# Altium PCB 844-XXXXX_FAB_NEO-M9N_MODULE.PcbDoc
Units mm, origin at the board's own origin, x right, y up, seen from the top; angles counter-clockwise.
Board outline 67.18 x 31.75 mm, 4 copper layers (L01-Top Layer, L02-Inner Layer, L03-Inner Layer, L04-Bottom Layer), stack 1.555 mm thick; 33 components, 25 nets, 85 pads, 218 vias.
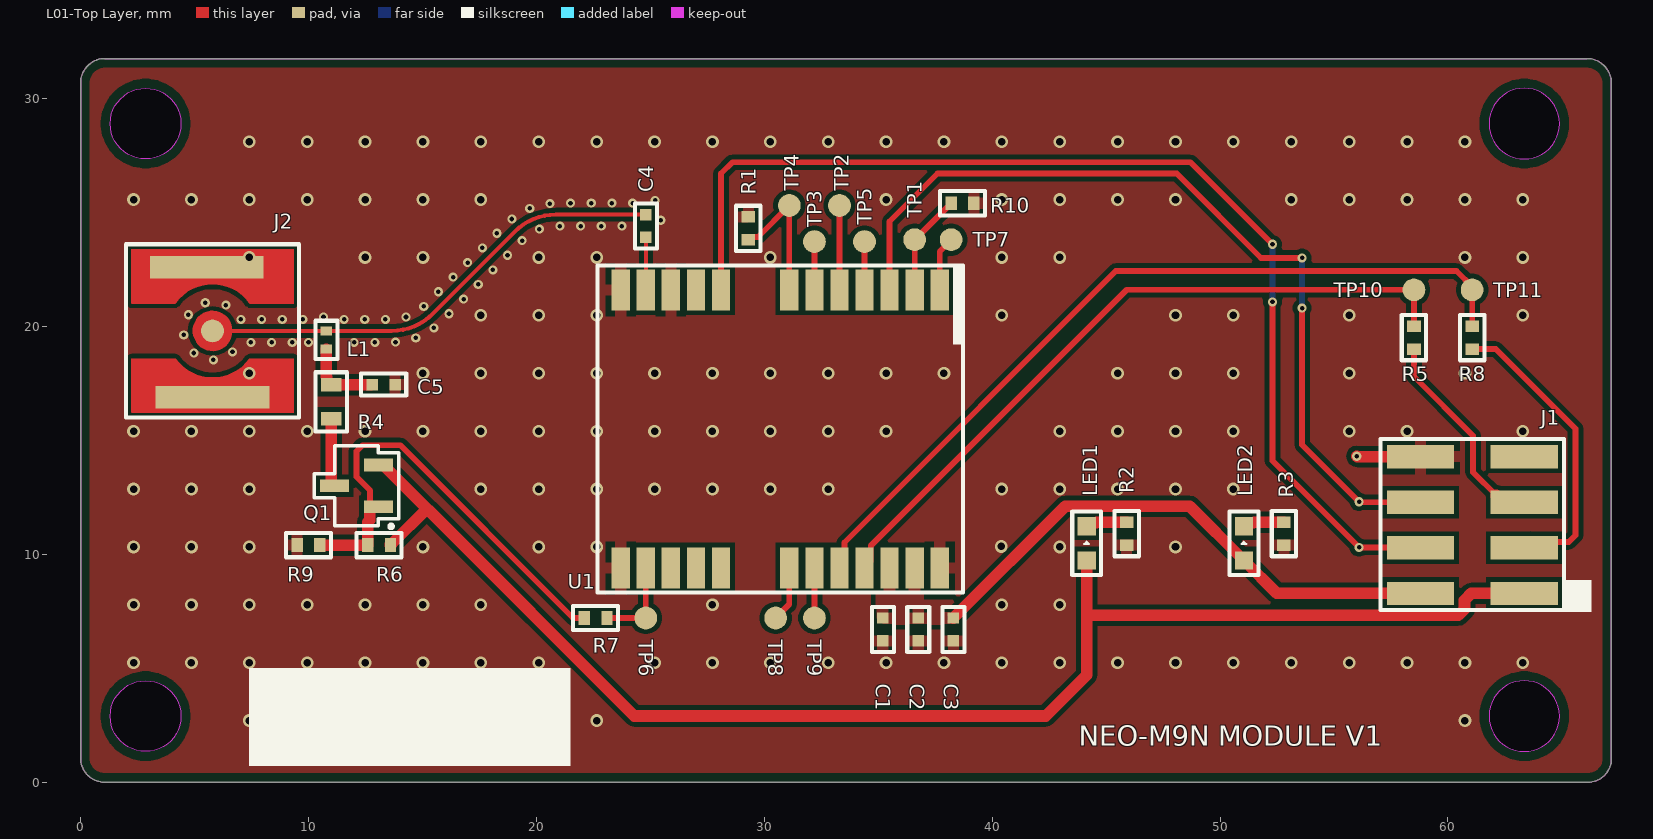
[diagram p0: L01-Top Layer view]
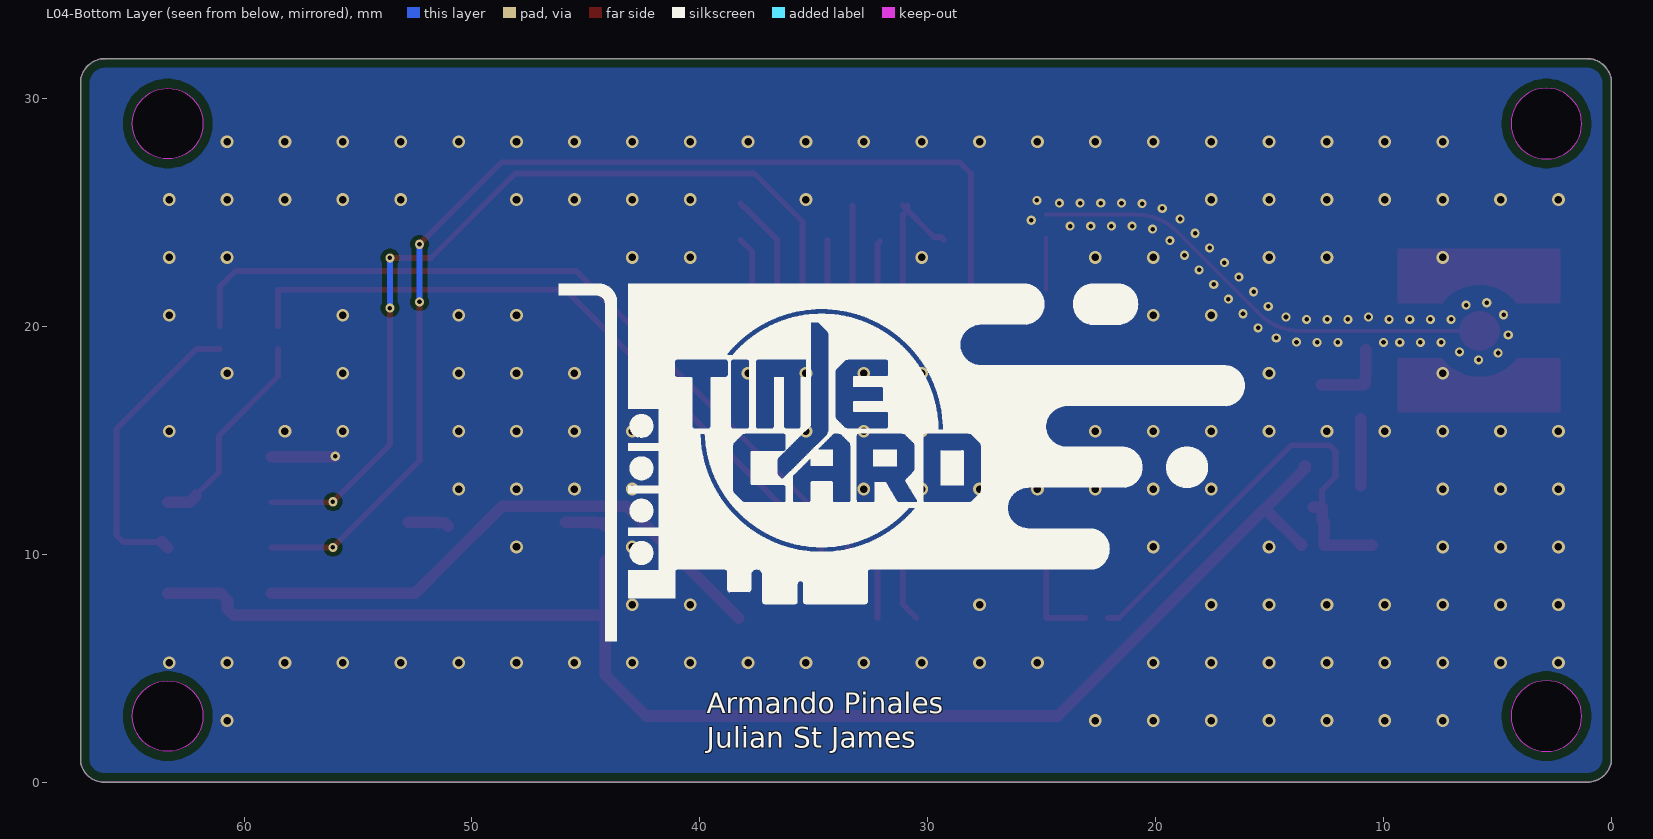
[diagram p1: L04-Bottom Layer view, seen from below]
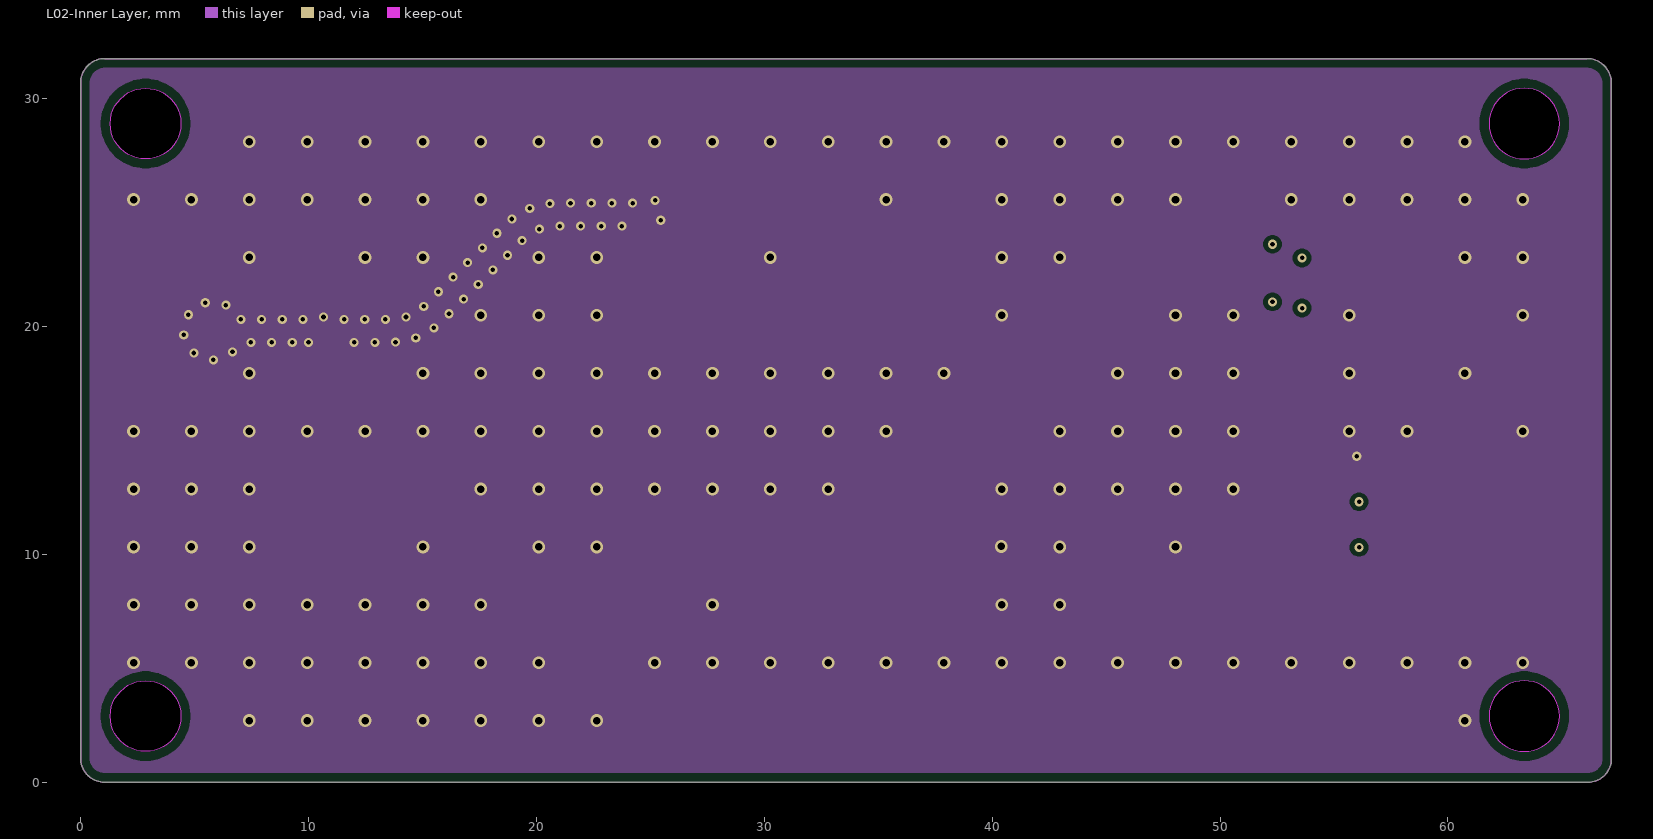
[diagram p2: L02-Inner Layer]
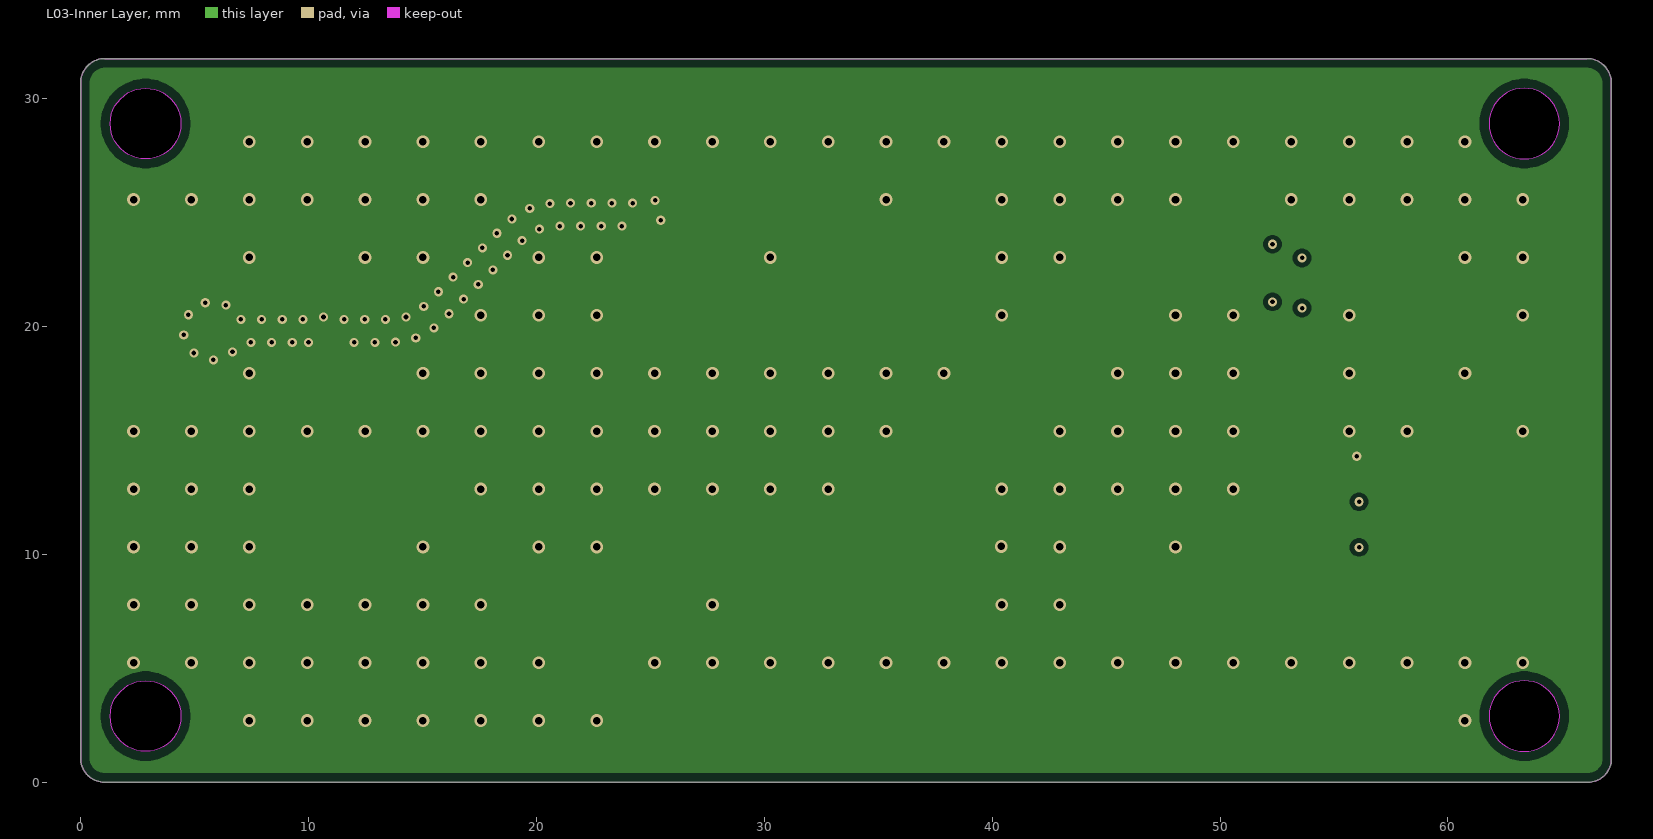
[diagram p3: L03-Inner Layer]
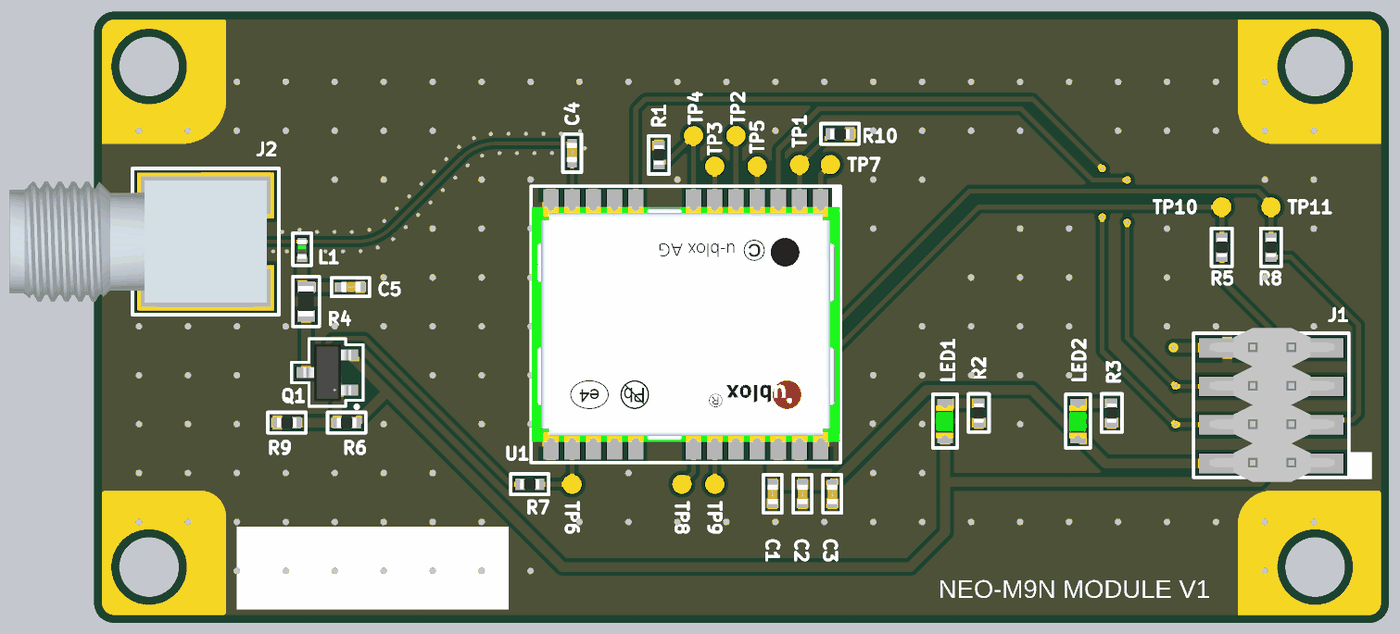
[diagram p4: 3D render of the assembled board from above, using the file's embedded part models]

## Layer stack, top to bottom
Top Solder: solder mask 0.0152, Solder Resist, Dk 3.9
L01-Top Layer: signal copper 0.0457
Dielectric 1: prepreg 0.1046, 2x106, Dk 3.7
L02-Inner Layer: signal copper 0.0305
Dielectric 2: core 1.1938, FR4, Dk 4.04
L03-Inner Layer: signal copper 0.0305
Dielectric 3: prepreg 0.1046, 2x106, Dk 3.7
L04-Bottom Layer: signal copper 0.0457
Bottom Solder: solder mask 0.0152, Solder Resist, Dk 3.9

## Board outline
1.045,0 cw(c1.045,1.045) 0,1.045 -0.002,30.676 cw(c1.069,30.676) 1.068,31.747 66.094,31.749 cw(c66.094,30.669) 67.174,30.67 67.171,1.015 cw(c66.152,1.015) 66.153,-0.004
cut-out: 61.801,2.896 ccw(c63.351,2.896) 63.351,1.346 ccw(c63.351,2.896) 64.901,2.896 ccw(c63.351,2.896) 63.351,4.446 ccw(c63.351,2.896)
cut-out: 1.301,2.896 cw(c2.851,2.896) 2.851,4.446 cw(c2.851,2.896) 4.401,2.896 cw(c2.851,2.896) 2.851,1.346 cw(c2.851,2.896)
cut-out: 61.801,28.896 ccw(c63.351,28.896) 63.351,27.346 ccw(c63.351,28.896) 64.901,28.896 ccw(c63.351,28.896) 63.351,30.446 ccw(c63.351,28.896)
cut-out: 2.851,27.346 cw(c2.851,28.896) 1.301,28.896 cw(c2.851,28.896) 2.851,30.446 cw(c2.851,28.896) 4.401,28.896 cw(c2.851,28.896)

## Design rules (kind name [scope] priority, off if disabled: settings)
AcuteAngle [All] p1: minimum=6.00000000000000E+0001 checktracksonly=FALSE
BoardOutlineClearance [All] p1: gap=0.4 ignorepadtopadclearanceinfootprint=FALSE
Clearance Clearance_L1andL4_Copper [(InPolygon AND (OnLayer('Top Layer') OR OnLayer('Bottom Layer'))) vs (InDifferentialPairClass('All Differential Pairs'))] p1: gap=0.2 ignorepadtopadclearanceinfootprint=FALSE except(0.3: Arc-Hole Track-Hole SMDPad-Hole THPad-Hole Via-Hole Fill-Hole Poly-Hole Region-Hole Text-Hole; 0.5: Arc-Fill Arc-Poly Arc-Region Track-Fill Track-Poly Track-Region SMDPad-Fill SMDPad-Poly SMDPad-Region THPad-Fill THPad-Poly THPad-Region Via-Fill Via-Poly Via-Region Fill-Fill Fill-Poly Fill-Region Poly-Poly Poly-Region Region-Region)
Clearance [All] p2: gap=0.2 ignorepadtopadclearanceinfootprint=FALSE
ComponentClearance [All] p1: gap=0.4 collisioncheckmode=3 verticalgap=0.5 showdistances=FALSE
DiffPairsRouting 90_Ohm_L1andL4 [InDifferentialPairClass('90_Ohm')] p1: maxlimit=0.254 minlimit=0.14 mostfreqgap=0.254 toplayer_maxgap=0.14 toplayer_prefgap=0.14 toplayer_minwidth=0.114 toplayer_maxwidth=0.114 toplayer_prefwidth=0.114 midlayer1_mingap=0.254 midlayer1_minwidth=0.381 midlayer1_maxwidth=0.381 midlayer1_prefwidth=0.381 midlayer2_mingap=0.254 midlayer2_minwidth=0.381 midlayer2_maxwidth=0.381 midlayer2_prefwidth=0.381 bottomlayer_maxgap=0.14 bottomlayer_prefgap=0.14 bottomlayer_minwidth=0.114 bottomlayer_maxwidth=0.114 bottomlayer_prefwidth=0.114 maxuncoupledlength=5.08
DiffPairsRouting 100_Ohm_L1andL4 [InDifferentialPairClass('100_Ohm')] p2: maxlimit=0.254 minlimit=0.241 mostfreqgap=0.254 toplayer_maxgap=0.241 toplayer_prefgap=0.241 toplayer_minwidth=0.114 toplayer_maxwidth=0.114 toplayer_prefwidth=0.114 midlayer1_mingap=0.254 midlayer1_minwidth=0.381 midlayer1_maxwidth=0.381 midlayer1_prefwidth=0.381 midlayer2_mingap=0.254 midlayer2_minwidth=0.381 midlayer2_maxwidth=0.381 midlayer2_prefwidth=0.381 bottomlayer_maxgap=0.241 bottomlayer_prefgap=0.241 bottomlayer_minwidth=0.114 bottomlayer_maxwidth=0.114 bottomlayer_prefwidth=0.114 maxuncoupledlength=5.08
DiffPairsRouting 100_Ohm_Default [All] p3: maxlimit=0.254 minlimit=0.241 mostfreqgap=0.254 toplayer_maxgap=0.241 toplayer_prefgap=0.241 toplayer_minwidth=0.114 toplayer_maxwidth=0.114 toplayer_prefwidth=0.114 midlayer1_mingap=0.254 midlayer1_minwidth=0.381 midlayer1_maxwidth=0.381 midlayer1_prefwidth=0.381 midlayer2_mingap=0.254 midlayer2_minwidth=0.381 midlayer2_maxwidth=0.381 midlayer2_prefwidth=0.381 bottomlayer_maxgap=0.241 bottomlayer_prefgap=0.241 bottomlayer_minwidth=0.114 bottomlayer_maxwidth=0.114 bottomlayer_prefwidth=0.114 maxuncoupledlength=5.08
HoleSize [All] p1: absolutevalues=TRUE maxlimit=3 minlimit=0.15 maxpercent=80.000 minpercent=20.000
HoleToHoleClearance [All] p1: gap=0.3 allowstackedmicrovias=TRUE
MatchedLengths [InDifferentialPairClass('All Differential Pairs')] p1: tolerance=0.025 checknetsindiffpair=TRUE checkdiffpairvsdiffpair=FALSE checkxsignals=FALSE checkothers=FALSE
MinimumSolderMaskSliver [All] p1: minsoldermaskwidth=0.1 // 0.076mm for Green Soldermask, 0.1 for other color soldermask
PlaneClearance [All] p1: clearance=0.254
PolygonConnect [All] p1: thpad.connectstyle=Relief thpad.reliefconductorwidth=0.508 thpad.reliefentries=4 thpad.polygonreliefangle="90 Angle" thpad.airgapwidth=0.254 smdpad.connectstyle=Relief smdpad.reliefconductorwidth=0.508 smdpad.reliefentries=4 smdpad.polygonreliefangle="90 Angle" smdpad.airgapwidth=0.254 via.connectstyle=Direct via.reliefconductorwidth=0.254 via.reliefentries=4 via.polygonreliefangle="90 Angle" via.airgapwidth=0.254
RoutingCorners [All] p1: cornerstyle=45-Degree minsetback=2.5 maxsetback=2.5
RoutingVias [All] p1: holewidth=0.2 width=0.4 viastyle="Through Hole" minholewidth=0.15 minwidth=0.35 maxholewidth=0.3 maxwidth=0.6
SilkToSilkClearance [All] p1: silktosilkclearance=0.1
SilkToSolderMaskClearance [IsPad] p1: minsilkscreentomaskgap=1 clearancetoexposedcopper=TRUE
SolderMaskExpansion [All] p1: expansion=0.05 istentingtop=FALSE
UnRoutedNet [All] p1: checkbadconnections=TRUE
Width Width_PWR [InNetClass('PWR')] p1: maxlimit=0.5 minlimit=0.2 preferedwidth=0.3 minimp=50.000000 maximp=50.000000 favimp=50.000000
Width Width_GND [InNetClass('GND')] p2: maxlimit=0.5 minlimit=0.2 preferedwidth=0.3 minimp=50.000000 maximp=50.000000 favimp=50.000000
20 further rules are at their usual default settings.

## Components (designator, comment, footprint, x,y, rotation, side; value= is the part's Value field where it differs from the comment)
C1 "1uF 6V3 0402" c0402 35.2,6.7 r90 top
C2 "100nF 10V 0402" c0402 36.756,6.7 r90 top
C3 "10nF 50V 0402" c0402 38.299,6.7 r90 top
C4 "47pF 50V 0402" c0402 24.801,24.4 r270 top
C5 "10nF 50V 0402" c0402 13.3,17.438 r180 top
J1 "NRPN042MAMS-RC 2MM" CONN_NRPN042MAMS-RC 63.345,8.28 r180 top locked
J2 "SMB_131-3711-301" CONN_131-3711-301 5.79,19.8 r270 top locked
L1 "27nH 300mA 460mohm 0402" L0402 10.788,19.4 r90 top
LED1 "Green" led0603 44.149,10.475 r90 top
LED2 "Green" led0603 51.049,10.475 r90 top
Q1 "DMG2302UKQ-7" SOT23 12.1,13 r90 top
R1 "0 ohm 0402" r0402 29.3,24.3 r90 top
R2 "10K 1/8W 0402" r0402 45.9,10.9 r90 top
R3 "10K 1/8W 0402" r0402 52.8,10.9 r90 top
R4 "10 OHM 1/4W 0603" r0603 11,16.688 r90 top
R5 "0 ohm 0402" r0402 58.506,19.5 r270 top
R6 "0 ohm 0402" r0402 13.1,10.4 r0 top
R7 "0 ohm 0402" r0402 22.6,7.2 r180 top
R8 "0 ohm 0402" r0402 61.061,19.5 r270 top
R9 "0 ohm 0402" r0402 10,10.4 r180 top
R10 "0 ohm 0402" r0402 38.7,25.4 r180 top
TP1 "1MM" TP1MM 36.6,23.8 r0 top
TP2 "1MM" TP1MM 33.3,25.3 r0 top
TP3 "1MM" TP1MM 32.2,23.715 r0 top
TP4 "1MM" TP1MM 31.1,25.3 r0 top
TP5 "1MM" TP1MM 34.4,23.715 r0 top
TP6 "1MM" TP1MM 24.8,7.2 r0 top
TP7 "1MM" TP1MM 38.2,23.8 r0 top
TP8 "1MM" TP1MM 30.5,7.2 r0 top
TP9 "1MM" TP1MM 32.2,7.2 r0 top
TP10 "1MM" TP1MM 58.506,21.6 r90 top
TP11 "1MM" TP1MM 61.061,21.6 r90 top
U1 "NEO-M9N-00B" IC_NEO-M9N 30.7,15.5 r90 top

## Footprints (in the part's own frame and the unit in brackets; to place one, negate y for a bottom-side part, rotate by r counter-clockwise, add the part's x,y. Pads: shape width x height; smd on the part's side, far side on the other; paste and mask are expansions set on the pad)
c0402 [mm]
  rect 0.5x0.5 smd: 1(-0.5,0) 2(0.5,0)
  silkscreen extent -0.99,-0.48 0.99,0.48, body extent -0.55,-0.28 0.5,0.27, height 0.56
CONN_131-3711-301 [mm]
  round 1 smd mask+0: 1(0,0)
  rect 1x5 smd mask+0: 2(-2.794,-0.254) 3(2.916,0)
  L01-Top Layer circle w0.013: c0,0 r0.864
  L01-Top Layer region: 1.219,-3.556 3.581,-3.556 3.581,3.556 1.219,3.556 1.219,1.642 1.827,0.919 2.045,0 1.827,-0.918 1.219,-1.641 1.219,-1.641
  L01-Top Layer region: -3.581,-3.556 -1.219,-3.556 -1.219,-1.641 -1.827,-0.918 -2.045,0 -1.827,0.919 -1.219,1.642 -1.219,1.642 -1.219,3.556 -3.581,3.556
  L01-Top Layer region: -0.864,0 -0.798,-0.33 -0.611,-0.61 -0.33,-0.798 0,-0.863 0,-0.863 0.331,-0.798 0.611,-0.61 0.798,-0.33 0.864,0 0.864,0 0.798,0.331 0.611,0.611 0.331,0.798 0,0.864 0,0.864 -0.33,0.798 -0.611,0.611 -0.798,0.331 -0.864,0
  L01-Top Layer lines w0.013: 3.581,-3.556 1.219,-3.556 1.219,-1.641 ccw(c0,0) 1.219,1.642 1.219,3.556 3.581,3.556 3.581,-3.556 ; -1.219,-3.556 -3.581,-3.556 -3.581,3.556 -1.219,3.556 -1.219,1.642 ccw(c0,0) -1.219,-1.641 -1.219,-3.556
  silkscreen extent -3.8,-3.8 3.8,3.8, body extent -3.18,-10.16 3.18,3.18, height 8.27
CONN_NRPN042MAMS-RC [mm] "MALE_P2MM_8POS_2ROW"
  rect 2.95x1.02 smd: 1(0,0) 2(4.55,0) 3(0,-2) 4(4.55,-2) 5(0,-4) 6(4.55,-4) 7(0,-6) 8(4.55,-6)
  silkscreen extent -2.95,-6.77 6.3,0.81, body extent -1.02,-7.05 5.48,0.95, height 5.81
IC_NEO-M9N [mil]
  rect 70.8x31.5 smd paste-99999: 1(240.15,-275.55) 2(240.15,-232.25) 3(240.15,-188.95) 4(240.15,-145.65) 5(240.15,-102.35) 6(240.15,-59.05) 7(240.15,-15.75) 8(240.15,102.35) 9(240.15,145.65) 10(240.15,188.95) 11(240.15,232.25) 12(240.15,275.55) 13(-240.15,275.55) 14(-240.15,232.25) 15(-240.15,188.95) 16(-240.15,145.65) 17(-240.15,102.35) 18(-240.15,-15.75) 19(-240.15,-59.05) 20(-240.15,-102.35) 21(-240.15,-145.65) 22(-240.15,-188.95) 23(-240.15,-232.25) 24(-240.15,-275.55)
  silkscreen extent -282,-316 282,316, body extent -240,-315 240,315, height 91
L0402 [mm]
  rect 0.4x0.5 smd: 1(-0.4,0) 2(0.4,0)
  silkscreen extent -0.83,-0.49 0.84,0.48, body extent -0.5,-0.25 0.5,0.25, height 0.56
led0603 [mm]
  rect 0.8x0.8 smd: 1(-0.75,0) 2(0.75,0)
  silkscreen extent -1.4,-0.64 1.4,0.64, body extent -0.88,-0.44 0.82,0.46, height 0.9
r0402 [mm]
  rect 0.5x0.6 smd: 1(-0.5,0) 2(0.5,0)
  silkscreen extent -0.99,-0.53 0.99,0.53, body extent -0.5,-0.25 0.5,0.25, height 0.36
r0603 [mm]
  rect 0.6x0.9 smd: 1(-0.75,0) 2(0.75,0)
  silkscreen extent -1.3,-0.69 1.3,0.69, body extent -0.79,-0.4 0.81,0.4, height 0.46
SOT23 [mil]
  rect 22x50 smd: 1(-36.02,-38) 2(36.02,-38) 3(0,38)
  silkscreen extent -73,-73 69,73, body extent -59,-49 59,49, height 43
TP1MM [mm] "Test Point 1MM diameter"
  round 1 smd paste-100: 1(0,0)

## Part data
C1: library part "CAP CER 1UF 6.3V X7R 0402", "0402 1 uF 6.3 V ±10% Tolerance X7R Multilayer Ceramic Capacitor", Capacitance=1uF, Case Code (Imperial)=0402, Case Code (Metric)=1005, Dielectric=X7R, Manufacturer=Murata, Manufacturer Part Number=GRM155R70J105KA12J, Max Operating Temperature=125°C, Min Operating Temperature=-55°C, Package Quantity=50000, Supplier Part Number 1=490-13339-1-ND, Tolerance=10%, Voltage Rating=6.3V
C2: library part "CAP CER 0.1UF 10V X7R 0402", "CL05 Series 0.1 uF 10 V ±10 % Tolerance X7R SMT Multilayer Ceramic Capacitor", Capacitance=100nF, Case Code (Imperial)=0402, Case Code (Metric)=1005, Dielectric=X7R, Manufacturer=Samsung, Manufacturer Part Number=CL05B104KP5NNNC, Max Operating Temperature=125°C, Min Operating Temperature=-55°C, Package Quantity=1, Supplier Part Number 1=1276-1002-1-ND, Tolerance=10%, Voltage Rating=10V
C3 C5: library part "CAP CER 10000PF 50V X7R 0402", "CAP CER 10000PF 50V X7R 0402", Capacitance=10nF, Case Code (Imperial)=0402, Case Code (Metric)=1005, Dielectric=X7R, Manufacturer=Murata, Manufacturer Part Number=GCM155R71H103KA55D, Max Operating Temperature=125°C, Min Operating Temperature=-55°C, Package Quantity=1, Ratings=AEC-Q200, Supplier Part Number 1=490-4762-1-ND, Tolerance=10%, Voltage=50V
C4: library part "CAP CER 47PF 50V C0G/NPO 0402", "0402 47 pF 50 V ±5 % Tolerance NP0 SMT Multilayer Ceramic Capacitor", Capacitance=47pF, Case Code (Imperial)=0402, Case Code (Metric)=1005, Dielectric=C0G, Dielectric Material=Ceramic, Insulation Resistance=100GR, Manufacturer=Yageo, Manufacturer Part Number=CC0402JRNPO9BN470, Max Operating Temperature=125°C, Min Operating Temperature=-55°C, Package Quantity=1, Supplier Part Number 1=311-1021-1-ND, Tolerance=5%, Voltage=50V
J1: library part CONN_NRPN042MAMS-RC, "Dual Row 8 Position 2 mm Pitch Surface Mount Header", Color=Black, Manufacturer=Sullins, Manufacturer Part Number=NRPN042MAMS-RC, Package Quantity=1000, Supplier Part Number 1=S6009-04-ND
J2: library part CONN_131-3711-301, "Rf Coaxial Board Mount Connector", Case/Package=SMA, Dielectric Material=PTFE, Frequency=4Hz, Housing Color=Gold, Manufacturer="Bel Cinch", Manufacturer Part Number=131-3711-301, Max Frequency=4GHz, Max Operating Temperature=165°C, Min Operating Temperature=-65°C, Operating Frequency="0 to 4 Hz to GHz", Package Quantity=25, Supplier Part Number 1=J10507-ND, Voltage Rating=335V
L1: library part "FIXED IND 27NH 350MA 460MOHM SMD", "Inductor RF Chip Multi-Layer 27nH 5% 100MHz 8Q-Factor Air 300mA 460mOhm DCR 0402 Paper T/R", Case Code (Imperial)=0402, Case Code (Metric)=1005, Current Rating=300mA, DC Resistance (DCR)=460mR, Inductance=27nH, Inductance Tolerance=5%, Manufacturer=Murata, Manufacturer Part Number=LQG15HS27NJ02D, Max Operating Temperature=125°C, Min Operating Temperature=-55°C, Package Quantity=10000, Self Resonant Frequency=1.7GHz, Supplier Part Number 1=490-2628-1-ND, Test Frequency=100MHz
LED1 LED2: library part "LED GREEN CLEAR CHIP SMD", "LED High-Power Uni-Color Green 574nm 2-Pin Chip LED T/R", Case Code (Imperial)=0603, Case Code (Metric)=1608, Forward Current=30mA, Forward Voltage=2V, Lens Color=Colorless, Manufacturer="Vishay Lite-On", Manufacturer Part Number=LTST-C190KGKT, Max Operating Temperature=85°C, Min Operating Temperature=-55°C, Package Quantity=1, Power Dissipation=75mW, Reverse Voltage=5V, Supplier Part Number 1=160-1435-1-ND, Test Current=20mA
Q1: "N-Channel 20 V 2.8A (Ta) 660mW (Ta) Surface Mount SOT-23-3", Case/Package=SOT-23, Continuous Drain Current (ID)=2.8A, Drain to Source Voltage (Vdss)=20V, Input Capacitance=130pF, Manufacturer=Diodes, Max Operating Temperature=150°C, Max Power Dissipation=660mW, Mfr_Name="Diodes Inc", Min Operating Temperature=-55°C, Supplier Part Number 1=31-DMG2302UKQ-7CT-ND
R1 R5 R6 R7 R8 R9 R10: library part "RES 0 OHM JUMPER 1/16W 0402", "RES SMD 0 OHM JUMPER 1/16W 0402", Case Code (Imperial)=0402, Case Code (Metric)=1005, Manufacturer=Yageo, Manufacturer Part Number=RC0402JR-070RL, Max Operating Temperature=155°C, Max Power Dissipation=63mW, Min Operating Temperature=-55°C, Package Quantity=1, Power Rating=62.5mW, Resistance=0mR, Resistance Tolerance=5%, Resistor Type="Thick Film", Supplier Part Number 1=311-0.0JRCT-ND, Temperature Coefficient=200ppm/°C, Voltage Rating=50V
R2 R3: library part "RES 10K OHM 1% 1/8W 0402", "Res Thick Film 0402 10K Ohm 1% 0.125W(1/8W) ±100ppm/°C Pad SMD T/R", Case Code (Imperial)=0402, Case Code (Metric)=1005, Manufacturer="TE Connectivity", Manufacturer Part Number=CRGP0402F10K, Max Operating Temperature=155°C, Max Power Dissipation=125mW, Min Operating Temperature=-55°C, Resistance=10kR, Resistor Type="Thick Film", Supplier Part Number 1=A130367CT-ND, Temperature Coefficient=100ppm/°C, Tolerance=1%
R4: library part "RES SMD 10 OHM 1% 1/4W 0603", "Res Surge Chip Thick Film 0603 10 Ohm 1% 1/4W ±200ppm/°C Molded Paper T/R", Manufacturer=Yageo, Manufacturer Part Number=SR0603FR-7T10RL, Supplier Part Number 1=YAG5824CT-ND
TP1 TP2 TP3 TP4 TP5 TP6 TP7 TP8 TP9 TP10 TP11: library part TP_1MM, "Test Point 1MM diameter"
U1: library part "IC NEO-M9N-00B", "GNSS module, Flash, TCXO, SAW, LNA, LCC, 12x16 mm Professional Grade", Manufacturer=u-blox, Supplier Part Number 1=672-NEO-M9N-00BCT-ND

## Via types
v1: diameter 0.559, hole 0.33, L01-Top Layer to L04-Bottom Layer, tented both sides, 160 vias
v2: diameter 0.4, hole 0.2, L01-Top Layer to L04-Bottom Layer, tented both sides, 51 vias
v3: diameter 0.4, hole 0.2, L01-Top Layer to L04-Bottom Layer, 7 vias

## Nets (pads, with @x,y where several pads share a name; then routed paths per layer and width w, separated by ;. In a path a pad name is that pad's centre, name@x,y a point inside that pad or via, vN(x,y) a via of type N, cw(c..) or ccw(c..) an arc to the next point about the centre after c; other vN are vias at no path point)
+3V3: C1.2 C2.2 C3.2 J1.2 LED2.1 U1.22 U1.23 | length 24.1
  L01-Top Layer w0.508: C3.2 43.207,12.108 48.666,12.108 LED2.1 52.494,8.28 J1.2
+5V: J1.1 LED1.1 Q1.2 R6.2 | length 63.2
  L01-Top Layer w0.508: Q1.2@13.446,13.89 13.446,13.754 15.2,12 13.646,10.446 13.604,10.446 13.6,10.442 R6.2 ; 15.25,11.95 24.3,2.9 42.352,2.9 44.149,4.698 44.149,7.316 ; LED1.1 44.149,7.316 ; J1.1 61.022,8.28 60.724,7.982 60.724,7.582 60.458,7.316 44.149,7.316
D_SEL: R10.2 TP1.1 U1.2 | length 4.5
  L01-Top Layer w0.254: U1.2 TP1.1 38.027,25.227 38.077,25.227 38.2,25.35 R10.2
EXTIN: TP5.1 U1.4 | length 2.2
  L01-Top Layer w0.254: U1.4 TP5.1@34.4,23.8
GND: C1.1 C2.1 C3.1 C5.1 J1.8 J2.2 J2.3 R1.2 R2.1 R3.1 R9.2 R10.1 U1.10 U1.12 U1.13 U1.24 | length 2.8
  L01-Top Layer w0.508: v3(56,14.3) 56.02,14.28 J1.8
  other v1: 7.404,2.7 9.944,2.7 12.484,2.7 15.024,2.7 17.564,2.7 20.104,2.7 22.644,2.7 60.744,2.7 2.324,5.24 4.864,5.24 7.404,5.24 9.944,5.24 12.484,5.24 15.024,5.24 17.564,5.24 20.104,5.24 25.184,5.24 27.724,5.24 30.264,5.24 32.804,5.24 35.344,5.24 37.884,5.24 40.424,5.24 42.964,5.24 45.504,5.24 48.044,5.24 50.584,5.24 53.124,5.24 55.664,5.24 58.204,5.24 60.744,5.24 63.284,5.24 2.324,7.78 4.864,7.78 7.404,7.78 9.944,7.78 12.484,7.78 15.024,7.78 17.564,7.78 27.724,7.78 40.424,7.78 42.964,7.78 2.324,10.32 4.864,10.32 7.404,10.32 15.024,10.32 20.104,10.32 22.644,10.32 42.964,10.32 48.044,10.32 40.403,10.341 2.324,12.86 4.864,12.86 7.404,12.86 17.564,12.86 20.104,12.86 22.644,12.86 25.184,12.86 27.724,12.86 30.264,12.86 32.804,12.86 40.424,12.86 42.964,12.86 45.504,12.86 48.044,12.86 50.584,12.86 2.324,15.4 4.864,15.4 7.404,15.4 9.944,15.4 12.484,15.4 15.024,15.4 17.564,15.4 20.104,15.4 22.644,15.4 25.184,15.4 27.724,15.4 30.264,15.4 32.804,15.4 35.344,15.4 42.964,15.4 45.504,15.4 48.044,15.4 50.584,15.4 55.664,15.4 58.204,15.4 63.284,15.4 7.404,17.94 15.024,17.94 17.564,17.94 20.104,17.94 22.644,17.94 25.184,17.94 27.724,17.94 30.264,17.94 32.804,17.94 35.344,17.94 37.884,17.94 45.504,17.94 48.044,17.94 50.584,17.94 55.664,17.94 60.744,17.94 17.564,20.48 20.104,20.48 22.644,20.48 40.424,20.48 48.044,20.48 50.584,20.48 55.664,20.48 63.284,20.48 7.404,23.02 12.484,23.02 15.024,23.02 20.104,23.02 22.644,23.02 30.264,23.02 40.424,23.02 42.964,23.02 60.744,23.02 63.284,23.02 2.324,25.56 4.864,25.56 7.404,25.56 9.944,25.56 12.484,25.56 15.024,25.56 17.564,25.56 35.344,25.56 40.424,25.56 42.964,25.56 45.504,25.56 48.044,25.56 53.124,25.56 55.664,25.56 58.204,25.56 60.744,25.56 63.284,25.56 7.404,28.1 9.944,28.1 12.484,28.1 15.024,28.1 17.564,28.1 20.104,28.1 22.644,28.1 25.184,28.1 27.724,28.1 30.264,28.1 32.804,28.1 35.344,28.1 37.884,28.1 40.424,28.1 42.964,28.1 45.504,28.1 48.044,28.1 50.584,28.1 53.124,28.1 55.664,28.1 58.204,28.1 60.744,28.1
  other v2: 5.828,18.529 4.971,18.828 6.666,18.878 7.472,19.296 8.38,19.296 9.288,19.296 10,19.296 12.003,19.296 12.911,19.296 13.819,19.307 14.708,19.492 4.529,19.621 15.503,19.93 7.032,20.304 7.94,20.304 8.848,20.304 9.756,20.304 11.56,20.304 12.468,20.304 13.376,20.304 10.658,20.408 14.278,20.409 4.733,20.506 16.165,20.552 15.06,20.871 6.374,20.93 5.472,21.033 16.807,21.194 15.702,21.514 17.449,21.836 16.344,22.156 18.091,22.478 16.986,22.798 18.734,23.12 17.628,23.44 19.376,23.762 18.27,24.082 20.132,24.263 21.031,24.396 21.939,24.396 22.847,24.396 23.755,24.396 25.459,24.654 18.927,24.709 19.707,25.172 20.59,25.385 21.498,25.404 22.406,25.404 23.314,25.404 24.222,25.404 25.207,25.527
LNA_EN: R7.1 TP6.1 U1.14 | length 3.9
  L01-Top Layer w0.254: R7.1 TP6.1 ; TP6.1 U1.14
NetC5_2: C5.2 L1.1 R4.2 | length 3.5
  L01-Top Layer w0.508: L1.1 10.788,17.782 10.804,17.766 10.804,17.484 10.85,17.438 R4.2 C5.2@12.738,17.438
NetLED1_2: LED1.2 R2.2 | length 1.8
  L01-Top Layer w0.508: LED1.2 44.295,11.371 44.563,11.371 44.593,11.4 R2.2
NetLED2_2: LED2.2 R3.2 | length 1.8
  L01-Top Layer w0.508: LED2.2 51.195,11.371 51.463,11.371 51.493,11.4 R3.2
NetQ1_1: Q1.1 R6.1 R7.2 R9.1 | length 20.4
  L01-Top Layer w0.254: Q1.1 12.858,12.085 12.705,12.237 12.705,12.795 12.103,13.397 12.103,14.516 12.365,14.777 14.035,14.777 21.612,7.2 R7.2
  L01-Top Layer w0.508: R9.1 R6.1 12.6,11.4 12.687,11.487 12.687,12.06 Q1.1@13.078,12.06
NetQ1_3: Q1.3 R4.1 | length 2.9
  L01-Top Layer w0.508: Q1.3@11,13 R4.1
RF_ANT: C4.1 J2.1 L1.2 | length 20.9
  L01-Top Layer w0.178: J2.1 13.649,19.8 ccw(c13.649,22.34) 15.445,20.544 19.057,24.156 cw(c20.853,22.36) 20.853,24.9 C4.1
RF_MODULE: C4.2 U1.11 | length 2.3
  L01-Top Layer w0.178: U1.11 C4.2
RST_GPS: J1.4 U1.8 | length 48.6
  L01-Top Layer w0.254: U1.8 28.1,26.7 28.6,27.2 48.7,27.2 v3(52.3,23.6) ; v3(52.3,21.073) 52.3,14.1 v3(56.1,10.3) 58.775,10.3 J1.4
  L04-Bottom Layer w0.254: v3(52.3,21.073) v3(52.3,23.6)
RX_GPS: R5.1 TP10.1 U1.21 | length 31.2
  L01-Top Layer w0.254: U1.21 34.673,9.673 34.673,10.373 45.9,21.6 TP10.1 R5.1
RX_GPS_CONN: J1.5 R5.2 | length 9.3
  L01-Top Layer w0.254: R5.2 58.506,17.794 61.1,15.2 61.1,13.6 J1.5@62.124,12.576
  L01-Top Layer w0.508: J1.5@62.124,12.576 62.124,12.536 62.38,12.28 J1.5
SAFEBOOT_N: TP7.1 U1.1 | length 2.4
  L01-Top Layer w0.254: U1.1 37.699,23.278 38.2,23.779 TP7.1
SCL_SPI_CLK: TP9.1 U1.19 | length 2.2
  L01-Top Layer w0.254: TP9.1 U1.19
SDA_SPI_CS_N: TP8.1 U1.18 | length 2.4
  L01-Top Layer w0.254: TP8.1 31.1,7.8 U1.18
TP1: J1.6 U1.3 | length 37.9
  L01-Top Layer w0.254: U1.3 35.5,24.6 37.6,26.7 48.1,26.7 51.8,23 v3(53.6,23) ; v3(53.6,20.8) 53.6,14.8 v3(56.1,12.3) 56.12,12.28 J1.6
  L04-Bottom Layer w0.254: v3(53.6,20.8) v3(53.6,23)
TX_GPS: R8.1 TP11.1 U1.20 | length 35.7
  L01-Top Layer w0.254: U1.20 33.515,9.615 33.515,10.515 45.427,22.427 60.373,22.427 61.061,21.739 R8.1
TX_GPS_CONN: J1.3 R8.2 | length 13.1
  L01-Top Layer w0.254: R8.2 62.1,19 65.6,15.5 65.6,10.834 65.302,10.536 J1.3@63.601,10.536
  L01-Top Layer w0.508: J1.3 J1.3@63.601,10.536
USB_DM: TP2.1 U1.5 | length 3.7
  L01-Top Layer w0.254: U1.5 TP2.1
USB_DP: TP3.1 U1.6 | length 2.2
  L01-Top Layer w0.254: TP3.1@32.1,23.715 32.2,23.615 U1.6
VDD_USB: R1.1 TP4.1 U1.7 | length 6.2
  L01-Top Layer w0.254: R1.1 29.423,23.923 29.723,23.923 TP4.1 ; TP4.1@30.873,25.3 30.873,25.098 30.885,25.085 31.1,24.871 U1.7
pads on no net: J1.7 U1.9 U1.15 U1.16 U1.17

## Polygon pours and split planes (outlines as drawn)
no net on Top Solder "NONET_L-01_P-001" (solid): 0.3,24.876 0.3,30.685 cw(c1.062,30.684) 1.062,31.446 6.84,31.446 6.84,26.981 cw(c4.508,27.22) 4.508,24.876
no net on Top Solder "NONET_L-01_P-001" (solid): 59.341,26.682 ccw(c61.229,26.764) 61.229,24.875 66.871,24.875 66.871,30.751 ccw(c66.108,30.678) 66.108,31.445 59.341,31.445
no net on Top Solder (solid): 59.341,0.296 59.341,5.191 cw(c61.106,5.099) 61.106,6.866 66.871,6.866 66.871,1.004 cw(c66.102,1.068) 66.102,0.296
no net on Top Solder "NONET_L-01_P-001" (solid): 1.066,0.296 cw(c1.066,1.062) 0.301,1.025 0.301,6.866 5.501,6.866 cw(c5.501,5.524) 6.841,5.601 6.841,0.296
no net on Bottom Solder (solid): 59.341,0.296 59.341,5.191 cw(c61.106,5.099) 61.106,6.866 66.871,6.866 66.871,1.004 cw(c66.102,1.068) 66.102,0.296
no net on Bottom Solder "NONET_L-01_P-001" (solid): 59.341,26.683 ccw(c61.229,26.766) 61.229,24.876 66.871,24.876 66.871,30.753 ccw(c66.108,30.679) 66.108,31.446 59.341,31.446
no net on Bottom Solder "NONET_L-01_P-001" (solid): 0.297,24.879 0.297,30.688 cw(c1.059,30.687) 1.059,31.449 6.837,31.449 6.837,26.984 cw(c4.505,27.223) 4.505,24.879
no net on Bottom Solder "NONET_L-01_P-001" (solid): 1.066,0.296 cw(c1.066,1.062) 0.301,1.025 0.301,6.866 5.501,6.866 cw(c5.501,5.524) 6.841,5.601 6.841,0.296
GND on L01-Top Layer "GND_L01_P005" (solid, remove dead copper, pour order 5): 1.045,0 cw(c1.045,1.045) 0,1.045 -0.002,30.676 cw(c1.069,30.676) 1.068,31.747 66.094,31.749 cw(c66.094,30.669) 67.174,30.67 67.171,1.015 cw(c66.152,1.015) 66.153,-0.004
+3V3 on L01-Top Layer "+3V3_L01_P002" (solid, pour order 2): 37,10.3 37,8 38.7,8 38.7,6.9 34.9,6.9 34.9,10.3 35.2,10.3
GND on L02-Inner Layer "GND_L02_P000" (solid, pour order 0): 0,1.045 ccw(c1.045,1.045) 1.045,0 66.153,-0.004 ccw(c66.152,1.015) 67.171,1.015 67.174,30.67 ccw(c66.094,30.669) 66.094,31.749 1.068,31.747 ccw(c1.069,30.676) -0.002,30.676
GND on L03-Inner Layer "GND_L03_P004" (solid, pour order 4): 1.045,0 cw(c1.045,1.045) 0,1.045 -0.002,30.676 cw(c1.069,30.676) 1.068,31.747 66.094,31.749 cw(c66.094,30.669) 67.174,30.67 67.171,1.015 cw(c66.152,1.015) 66.153,-0.004
GND on L04-Bottom Layer "GND_L04_P001" (solid, pour order 1): 1.045,0 cw(c1.045,1.045) 0,1.045 -0.002,30.676 cw(c1.069,30.676) 1.068,31.747 66.094,31.749 cw(c66.094,30.669) 67.174,30.67 67.171,1.015 cw(c66.152,1.015) 66.153,-0.004

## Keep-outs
Keep-Out Layer:
  the board outline again, w0.013

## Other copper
L01-Top Layer:
  pour cut-out: 182 vertices and 0 holes, not listed, extent 4.728,18.738 25.25,25.349

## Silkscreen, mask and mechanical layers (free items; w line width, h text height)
Top Overlay:
  rectangle: 7.4,0.7 21.5,5
  text "NEO-M9N MODULE V1" at 43.8,1.3 h1.5
Bottom Overlay:
  drawing of 10 lines, arcs and shapes, not listed
  text "Armando Pinales / Julian St James" at 39.7,1.2 h1.52
M01_PCB_Outline:
  circle w0.013: c63.351,28.896 r1.55
  circle w0.013: c2.851,2.896 r1.55
  circle w0.013: c63.351,2.896 r1.55
  circle w0.013: c2.851,28.896 r1.55
  pour cut-out: 61.801,2.896 ccw(c63.351,2.896) 63.351,1.346 ccw(c63.351,2.896) 64.901,2.896 ccw(c63.351,2.896) 63.351,4.446 ccw(c63.351,2.896)
  lines w0.013: -0.379,0 1.045,0 ; 0,-0.256 0,1.045 ; 0.302,1.025 ccw(c1.067,1.062) 1.067,0.296 ; 0.302,1.025 ccw(c1.067,1.062) 1.067,0.296 ; 0.302,1.025 0.302,6.866 ; 0.302,1.025 0.302,6.866 ; 0.302,6.866 5.502,6.866 ; 0.302,6.866 5.502,6.866 ; 1.067,0.296 6.842,0.296 ; 1.067,0.296 6.842,0.296 ; 5.502,6.866 cw(c5.502,5.524) 6.842,5.601 ; 5.502,6.866 cw(c5.502,5.524) 6.842,5.601 ; 6.842,0.296 6.842,5.601 ; 6.842,0.296 6.842,5.601 ; 0.301,24.876 0.301,30.685 cw(c1.063,30.684) 1.063,31.446 6.841,31.446 6.841,26.981 cw(c4.509,27.22) 4.509,24.876 0.301,24.876 ; 59.341,26.683 ccw(c61.229,26.766) 61.229,24.876 66.871,24.876 66.871,30.753 ccw(c66.108,30.679) 66.108,31.446 59.341,31.446 59.341,26.683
